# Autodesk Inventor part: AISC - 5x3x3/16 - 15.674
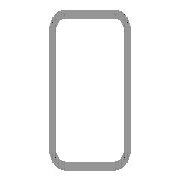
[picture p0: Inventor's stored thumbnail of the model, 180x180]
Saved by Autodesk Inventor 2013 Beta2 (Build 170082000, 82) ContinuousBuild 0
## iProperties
_CCFamilyMember: 33
_CCFamilyDisplayName: ANSI AISC (Rectangular) - Tube
_FrameMemberDoc: Frame Member File
_Version: 15.0.0
_GetPNFromCC: 1
Created: 2010-11
Part Number: AISC - 5x3x3/16 - 15.674
Material: Steel, Mild
Description: Tube
Document SubType Name: Modeling
Standard: ANSI
Designer: Beta-8540w
Standards Organization: ANSI
Language: en-US
Size Designation: 5x3x3/16
Categories: <MemberInstance><Categories><Category DisplayName="Structural Shapes" InternalName="089c4875-fa83-4c05-b084-43b9cc11f5ed" Mnemonic="GRDR"><CategoryParameter Dis
Stock Number: 5x3x3/16
Density: 7.86 g/cm^3
IsCustomPart: 1
G_W: 3.000 in
G_H: 5.000 in
G_L: 15.674 in
+56B78839-94CC-4781-8179-10EE230693A1+CUTDETAIL1: Cut
+31F04844-9E02-49A4-9EBC-19785BF63232+CUTDETAIL2: Cut
Author: Beta-8540w
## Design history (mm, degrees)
node "Start plane"
node "End plane"
sketch "Sketch"
  geometry: L1 (-38.1, -53.975)-(-38.1, 53.975); L2 (-28.575, 63.5)-(28.575, 63.5); L3 (38.1, 53.975)-(38.1, -53.975); L4 (28.575, -63.5)-(-28.575, -63.5); L5 (-28.575, 58.737)-(28.575, 58.737); L6 (33.338, 53.975)-(33.338, -53.975); L7 (28.575, -58.737)-(-28.575, -58.737); L8 (-33.338, -53.975)-(-33.338, 53.975); L9 (0, 91.662)-(0, -91.662) reference; L10 (-56.102, 0)-(56.102, 0) reference; A1 r 9.525 centre (-28.575, -53.975) between (-38.1, -53.975) and (-28.575, -63.5); A2 r 9.525 centre (-28.575, 53.975) between (-28.575, 63.5) and (-38.1, 53.975); A3 r 9.525 centre (28.575, 53.975) between (38.1, 53.975) and (28.575, 63.5); A4 r 9.525 centre (28.575, -53.975) between (28.575, -63.5) and (38.1, -53.975); A5 r 4.763 centre (-28.575, 53.975) between (-28.575, 58.737) and (-33.338, 53.975); A6 r 4.763 centre (28.575, 53.975) between (33.338, 53.975) and (28.575, 58.737); A7 r 4.763 centre (28.575, -53.975) between (28.575, -58.737) and (33.338, -53.975); A8 r 4.763 centre (-28.575, -53.975) between (-33.338, -53.975) and (-28.575, -58.737)
  constraints: 16 end point, 16 point on circle, 8 centre point, 8 tangent, 4 parallel, 3 equal radius, 2 perpendicular, 7 other
  dimensions: "d10" = 127 distance between parallel lines of L2 L4 (= G_H); "d11" = 76.2 distance between parallel lines of L1 L3 (= G_W); "d12" = 4.7625 distance between parallel lines of L3 L6 (= G_T); "d15" = 63.5 distance between parallel lines of L2 L10 (= 0.5 x d10); "d16" = 38.1 distance between parallel lines of L9 L3 (= 0.5 x d11); "d17" = 9.525 radius of A1 (= G_IR)
extrude "Body" new body sketch "Sketch" stored distance "d3" = 398.12556 (= G_L); taper "d4" = 0 deg
node "Driven Length"
  sketch "Sketch3"
    geometry: L1 (0, 0)-(10, 0) reference
    constraints: 2 end point, 1 horizontal
  workplane "Work Plane3"
  sketch "Sketch4"
    geometry: L1 (-2, 25.924)-(12, 25.924) reference; L2 (-2, 424.049)-(12, 424.049) reference
    dimensions: "d19" = 398.12556 distance between parallel lines of L1 L2 (derived)
workplane "Work Plane4"
split "Split1"
workplane "Work Plane5"
split "Split2"
body "Solid1"
other parameters: "G_W" = 76.2 [user parameter; used in 1 equation term], "G_H" = 127 [user parameter; used in 1 equation term], "G_T" = 4.7625 [user parameter; used in 1 equation term], "G_IR" = 9.525 [user parameter; used in 1 equation term], "G_L" = 398.12556 (= d19) [user parameter; used in 1 equation term], "G_OFFSET_START" = -25.92377 [user parameter; used in 1 equation term], "G_OFFSET_END" = -25.92377 [user parameter; used in 1 equation term], "d13" = 25.92377 (= -G_OFFSET_START), "d14" = 424.04933 (= G_OFFSET_END + B_L), "B_L" = 449.97309 [user parameter; used in 1 equation term], "d18" = 90 deg
